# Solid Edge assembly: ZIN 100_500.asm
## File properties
Title: Zylinder
Author: bmolnar
Template: iso metric assembly.asm
Last saved by: bmolnar
Revision: 33
Application: Solid Edge
Username: bmolnar
Dokumentum tartalom típus: 1
Document Number: ZIN 100/500
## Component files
Kit_1.par
Profilrohr.par
Kolbenstange.par
Kit_2.par
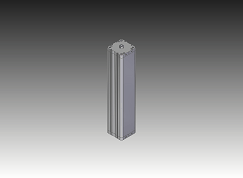
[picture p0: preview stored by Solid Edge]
